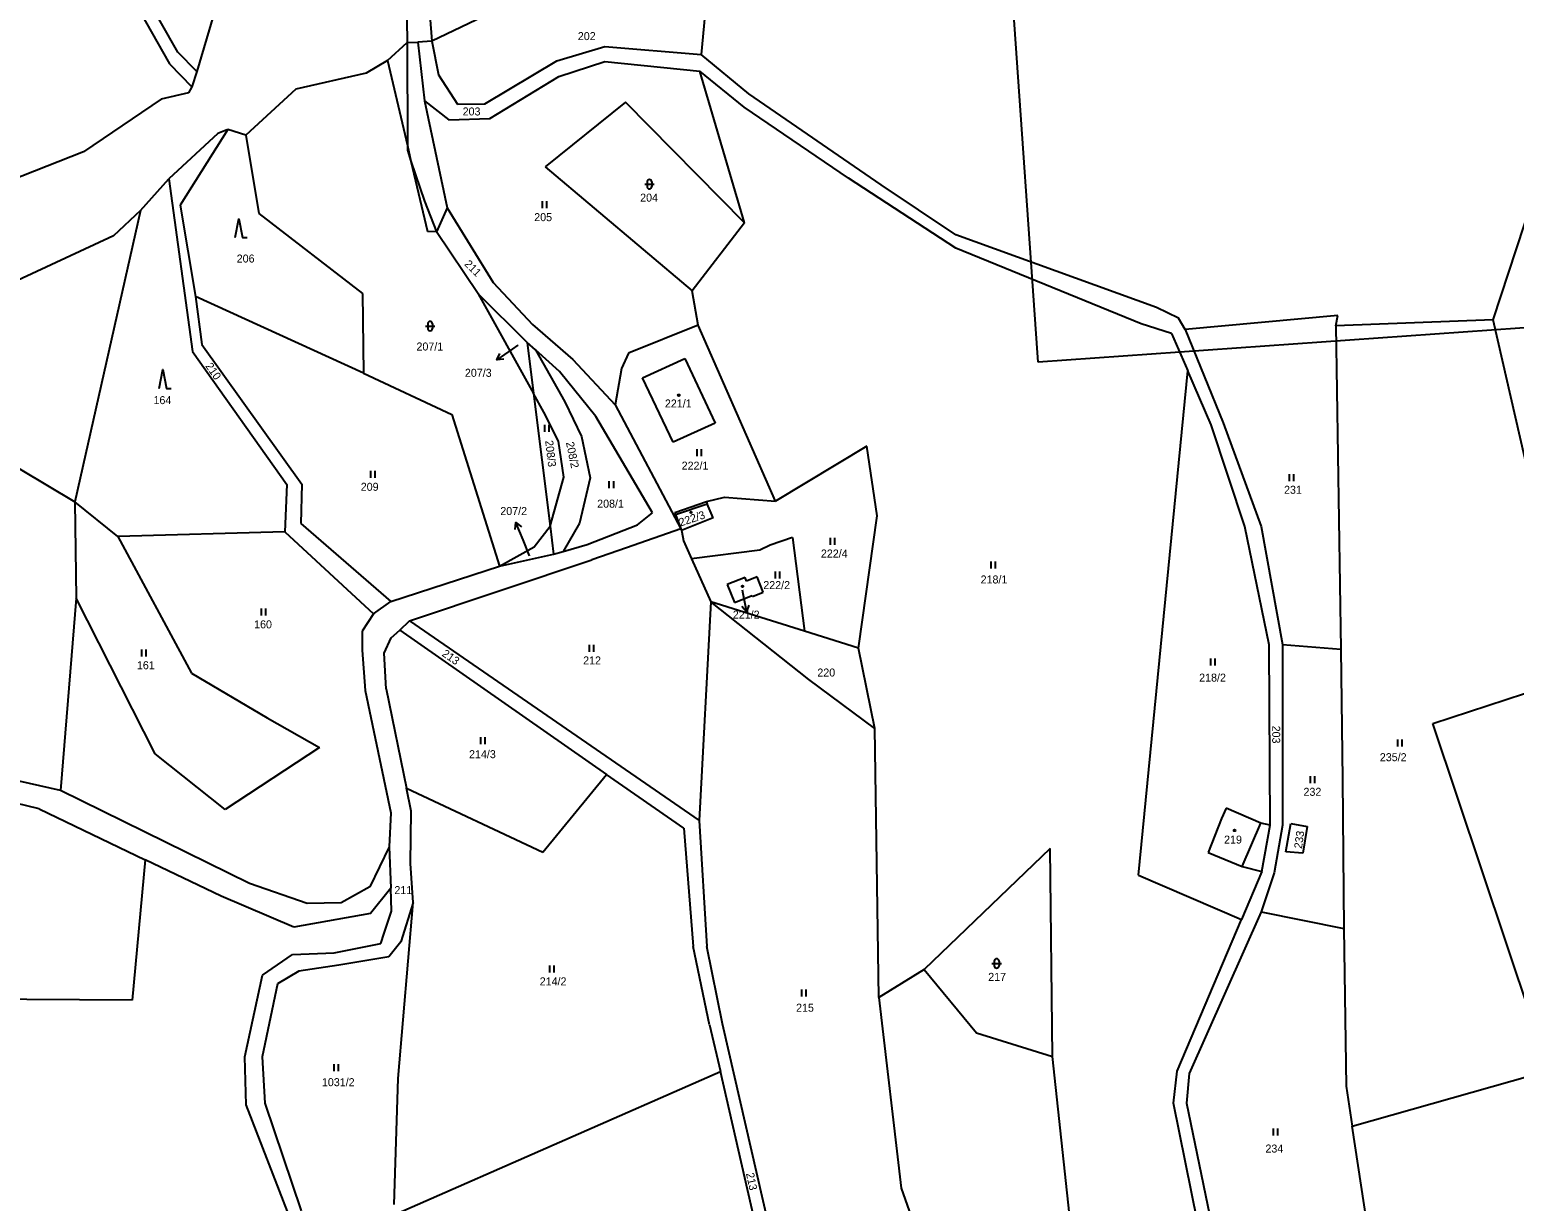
# Model space of a CAD drawing. Extents: x -670359 to -668019, y -978807 to -976674.
# Drawn here: x -669891.1 to -669575.5, y -977465.8 to -977216.7 of the extents above; entities that cross this region are included whole.
import ezdxf

# ---------------------------------------------------------------- set-up
doc = ezdxf.new("R2010")
doc.units = 0
for name, color, linetype in [('Hranice parcel', 7, 'Continuous'), ('Parcelní čísla', 7, 'Continuous'), ('Vnitřní kresba', 7, 'Continuous'), ('Značky budov', 7, 'Continuous'), ('Značky kultur', 7, 'Continuous')]:
    doc.layers.add(name, color=color, linetype=linetype)

msp = doc.modelspace()

# ---------------------------------------------------------------- linework, layer by layer
at = {"layer": 'Defpoints'}
for p, q in [((-669676.69, -977287.4), (-669697.04, -976999.11)), ((-669257.73, -977257.82), (-669676.69, -977287.4))]:
    msp.add_line(p, q, dxfattribs=at)
at = {"layer": 'Hranice parcel'}
for p, q in [((-669739.01, -977333.17), (-669742.81, -977334.66)), ((-669738.72, -977333.92), (-669739.01, -977333.17)), ((-669736.45, -977333.03), (-669738.72, -977333.92)), ((-669735.16, -977336.25), (-669736.45, -977333.03)), ((-669742.81, -977334.66), (-669741.28, -977338.46)), ((-669737.46, -977337.16), (-669735.16, -977336.25)), ((-669741.28, -977338.46), (-669737.54, -977336.98)), ((-669737.54, -977336.98), (-669737.46, -977337.16))]:
    msp.add_line(p, q, dxfattribs=at)
for points in [[(-669745.97, -977196.23), (-669748.39, -977221.98)], [(-669873.73, -977202.11), (-669861.38, -977223.93)], [(-669859.63, -977221.44), (-669870.61, -977202.09)], [(-669780.54, -977207.07), (-669805.6, -977219.15)], [(-669852, -977213.57), (-669855.6, -977225.55)], [(-669805.6, -977219.15), (-669808.62, -977219.32)], [(-669808.62, -977219.32), (-669807.2, -977231.84)], [(-669805.6, -977219.15), (-669804.19, -977226.31)], [(-669855.6, -977225.55), (-669859.63, -977221.44)], [(-669779.01, -977223.28), (-669768.87, -977220.26)], [(-669768.87, -977220.26), (-669748.39, -977221.98)], [(-669738.19, -977230.31), (-669748.39, -977221.98)], [(-669861.38, -977223.93), (-669856.65, -977228.85)], [(-669855.6, -977225.55), (-669856.65, -977228.85)], [(-669819.61, -977225.91), (-669834.51, -977229.35)], [(-669815.03, -977223.23), (-669819.61, -977225.91)], [(-669815.03, -977223.23), (-669810.82, -977241.3)], [(-669794.32, -977232.48), (-669779.01, -977223.28)], [(-669778.6, -977226.63), (-669768.86, -977223.46)], [(-669768.86, -977223.46), (-669748.61, -977225.5)], [(-669739.21, -977233.19), (-669748.61, -977225.5)], [(-669739.16, -977257.72), (-669748.61, -977225.5)], [(-669856.65, -977228.85), (-669857.35, -977230.1)], [(-669804.19, -977226.31), (-669800.16, -977232.52)], [(-669793.26, -977235.59), (-669778.6, -977226.63)], [(-669863.14, -977231.48), (-669879.68, -977242.68)], [(-669857.35, -977230.1), (-669863.14, -977231.48)], [(-669834.51, -977229.35), (-669845.14, -977239.1)], [(-669807.2, -977231.84), (-669802.36, -977254.58)], [(-669807.2, -977231.84), (-669801.98, -977235.88)], [(-669764.41, -977232.06), (-669781.53, -977245.83)], [(-669739.16, -977257.72), (-669764.41, -977232.06)], [(-669710.1, -977249.64), (-669738.19, -977230.31)], [(-669800.16, -977232.52), (-669794.32, -977232.48)], [(-669717.06, -977248.24), (-669739.21, -977233.19)], [(-669848.97, -977237.91), (-669859.14, -977253.96)], [(-669848.97, -977237.91), (-669851.13, -977238.73)], [(-669845.14, -977239.1), (-669848.97, -977237.91)], [(-669801.98, -977235.88), (-669793.26, -977235.59)], [(-669851.13, -977238.73), (-669861.56, -977248.4)], [(-669845.14, -977239.1), (-669842.41, -977255.78)], [(-669810.82, -977241.3), (-669810.05, -977244.62)], [(-669879.68, -977242.68), (-669903.28, -977251.92)], [(-669810.05, -977244.62), (-669806.57, -977259.56)], [(-669781.53, -977245.83), (-669750.28, -977272.17)], [(-669867.54, -977255.16), (-669861.56, -977248.4)], [(-669861.56, -977248.4), (-669856.49, -977285.11)], [(-669694.19, -977263.13), (-669717.06, -977248.24)], [(-669694.2, -977260.33), (-669710.1, -977249.64)], [(-669579.99, -977278.35), (-669570.08, -977248.16)], [(-669859.14, -977253.96), (-669855.83, -977273.44)], [(-669867.54, -977255.16), (-669881.51, -977317.07)], [(-669867.54, -977255.16), (-669873.27, -977260.54)], [(-669842.41, -977255.78), (-669820.33, -977272.75)], [(-669802.36, -977254.58), (-669804.65, -977259.63)], [(-669802.36, -977254.58), (-669792.59, -977270.43)], [(-669873.27, -977260.54), (-669899.87, -977272.82)], [(-669804.65, -977259.63), (-669806.57, -977259.56)], [(-669795.78, -977272.85), (-669804.65, -977259.63)], [(-669739.16, -977257.72), (-669750.28, -977272.17)], [(-669651.58, -977275.74), (-669694.2, -977260.33)], [(-669654.84, -977279.2), (-669694.19, -977263.13)], [(-669820.33, -977272.75), (-669820.16, -977289.69)], [(-669795.78, -977272.85), (-669783.98, -977294.05)], [(-669785.33, -977283.17), (-669795.78, -977272.85)], [(-669792.59, -977270.43), (-669784.23, -977279.33)], [(-669749.03, -977279.5), (-669750.28, -977272.17)], [(-669855.83, -977273.44), (-669854.5, -977283.58)], [(-669820.16, -977289.69), (-669855.83, -977273.44)], [(-669646.85, -977278.03), (-669651.58, -977275.74)], [(-669784.23, -977279.33), (-669775.63, -977286.79)], [(-669749.03, -977279.5), (-669763.8, -977285.44)], [(-669732.56, -977316.93), (-669749.03, -977279.5)], [(-669648.35, -977281.24), (-669654.84, -977279.2)], [(-669645.47, -977280.42), (-669646.85, -977278.03)], [(-669613.02, -977277.43), (-669645.47, -977280.42)], [(-669613.41, -977279.67), (-669613.02, -977277.43)], [(-669579.99, -977278.35), (-669613.41, -977279.67)], [(-669613.41, -977279.67), (-669612.4, -977348.39)], [(-669568.52, -977328.39), (-669579.99, -977278.35)], [(-669648.35, -977281.24), (-669644.9, -977289.2)], [(-669645.47, -977280.42), (-669637.37, -977300.27)], [(-669856.49, -977285.11), (-669836.43, -977313.36)], [(-669854.5, -977283.58), (-669833.23, -977313.34)], [(-669783.61, -977284.73), (-669785.33, -977283.17)], [(-669785.33, -977283.17), (-669783.98, -977294.05)], [(-669783.61, -977284.73), (-669777.31, -977295.79), (-669773.81, -977303.17), (-669771.93, -977311.94), (-669774.22, -977321.62), (-669777.7, -977327.62)], [(-669778.5, -977289.36), (-669783.61, -977284.73)], [(-669763.8, -977285.44), (-669765.3, -977288.73)], [(-669775.63, -977286.79), (-669766.62, -977296.41)], [(-669765.3, -977288.73), (-669766.62, -977296.41)], [(-669760.82, -977290.7), (-669751.8, -977286.57)], [(-669751.8, -977286.57), (-669745.41, -977300.35)], [(-669928.04, -977289.3), (-669881.51, -977317.07)], [(-669820.16, -977289.69), (-669801.4, -977298.53)], [(-669770.77, -977298.91), (-669778.5, -977289.36)], [(-669754.34, -977304.4), (-669760.82, -977290.7)], [(-669655.39, -977396.43), (-669644.9, -977289.2)], [(-669639.93, -977300.68), (-669644.9, -977289.2)], [(-669783.98, -977294.05), (-669780.47, -977322.26)], [(-669780.47, -977322.26), (-669777.53, -977311.83), (-669778.67, -977304.18), (-669781.79, -977297.97), (-669783.98, -977294.05)], [(-669801.4, -977298.53), (-669791.23, -977330.75)], [(-669766.62, -977296.41), (-669752.68, -977322.83)], [(-669758.69, -977319.41), (-669770.77, -977298.91)], [(-669745.41, -977300.35), (-669754.34, -977304.4)], [(-669632.77, -977322.3), (-669639.93, -977300.68)], [(-669637.37, -977300.27), (-669629.33, -977322.28)], [(-669713.15, -977305.2), (-669732.56, -977316.93)], [(-669710.92, -977320.05), (-669713.15, -977305.2)], [(-669836.43, -977313.36), (-669836.85, -977323.44)], [(-669833.23, -977313.34), (-669833.5, -977321.66)], [(-669881.51, -977317.07), (-669881.24, -977337.52)], [(-669872.35, -977324.45), (-669881.51, -977317.07)], [(-669753.94, -977319.34), (-669747.24, -977316.99)], [(-669747.24, -977316.99), (-669743.4, -977316.09)], [(-669747.24, -977316.99), (-669747.08, -977317.47)], [(-669745.78, -977320.48), (-669747.08, -977317.47)], [(-669743.4, -977316.09), (-669732.56, -977316.93)], [(-669761.88, -977321.94), (-669758.69, -977319.41)], [(-669753.94, -977319.34), (-669753.8, -977319.74)], [(-669753.8, -977319.74), (-669752.68, -977322.83)], [(-669745.78, -977320.48), (-669752.56, -977323.17)], [(-669714.94, -977348.16), (-669710.92, -977320.05)], [(-669836.85, -977323.44), (-669872.35, -977324.45)], [(-669836.85, -977323.44), (-669818.04, -977340.9)], [(-669833.5, -977321.66), (-669814.3, -977338.24)], [(-669791.23, -977330.75), (-669783.88, -977326.62), (-669780.47, -977322.26)], [(-669780.47, -977322.26), (-669779.73, -977328.21)], [(-669772.6, -977326.15), (-669761.88, -977321.94)], [(-669752.68, -977322.83), (-669764.26, -977326.84), (-669771.57, -977329.37)], [(-669752.68, -977322.83), (-669752.56, -977323.17)], [(-669752.56, -977323.17), (-669752.48, -977323.41)], [(-669752.48, -977323.41), (-669752.15, -977325.33)], [(-669627.6, -977347.44), (-669632.77, -977322.3)], [(-669629.33, -977322.28), (-669624.8, -977347.42)], [(-669872.35, -977324.45), (-669856.68, -977353.52)], [(-669777.7, -977327.62), (-669772.6, -977326.15)], [(-669752.15, -977325.33), (-669750.41, -977329.18)], [(-669733.67, -977326.26), (-669735.91, -977327.31)], [(-669728.96, -977324.63), (-669733.67, -977326.26)], [(-669728.96, -977324.63), (-669726.39, -977344.56)], [(-669810.36, -977342.38), (-669771.57, -977329.37)], [(-669791.23, -977330.75), (-669779.73, -977328.21)], [(-669779.73, -977328.21), (-669777.7, -977327.62)], [(-669735.91, -977327.31), (-669750.41, -977329.18)], [(-669750.41, -977329.18), (-669746.32, -977338.31)], [(-669814.3, -977338.24), (-669791.23, -977330.75)], [(-669881.24, -977337.52), (-669884.54, -977378.46)], [(-669864.43, -977370.67), (-669881.24, -977337.52)], [(-669818.04, -977340.9), (-669814.3, -977338.24)], [(-669746.32, -977338.31), (-669748.79, -977384.84)], [(-669726.39, -977344.56), (-669746.32, -977338.31)], [(-669725.44, -977354.82), (-669746.32, -977338.31)], [(-669818.04, -977340.9), (-669820.42, -977344.59)], [(-669812.43, -977344.31), (-669810.36, -977342.38)], [(-669810.36, -977342.38), (-669748.79, -977384.84)], [(-669820.42, -977344.59), (-669820.4, -977348.59)], [(-669814.26, -977346), (-669812.43, -977344.31)], [(-669812.43, -977344.31), (-669768.46, -977375.01)], [(-669714.94, -977348.16), (-669726.39, -977344.56)], [(-669820.4, -977348.59), (-669819.8, -977357.14)], [(-669815.76, -977349.2), (-669814.26, -977346)], [(-669711.47, -977365.28), (-669714.94, -977348.16)], [(-669627.39, -977385.8), (-669627.6, -977347.44)], [(-669624.8, -977347.42), (-669624.75, -977385.78)], [(-669624.8, -977347.42), (-669612.4, -977348.39)], [(-669612.4, -977348.39), (-669612.01, -977376.12)], [(-669815.32, -977356.79), (-669815.76, -977349.2)], [(-669856.68, -977353.52), (-669840.64, -977363.01)], [(-669711.47, -977365.28), (-669725.44, -977354.82)], [(-669819.8, -977357.14), (-669814.3, -977383.16)], [(-669815.32, -977356.79), (-669810.99, -977377.91)], [(-669592.8, -977364.17), (-669573.32, -977357.82)], [(-669840.64, -977363.01), (-669829.49, -977369.26)], [(-669571.83, -977426.86), (-669592.8, -977364.17)], [(-669710.6, -977422.41), (-669711.47, -977365.28)], [(-669849.57, -977382.49), (-669864.43, -977370.67)], [(-669829.49, -977369.26), (-669849.57, -977382.49)], [(-669884.54, -977378.46), (-669899.99, -977374.96)], [(-669782.05, -977391.57), (-669768.46, -977375.01)], [(-669752.06, -977386.46), (-669768.46, -977375.01)], [(-669612.01, -977376.12), (-669611.76, -977407.76)], [(-669889.07, -977382.32), (-669901.73, -977379.28)], [(-669844.36, -977398.2), (-669884.54, -977378.46)], [(-669809.98, -977382.81), (-669810.99, -977377.91)], [(-669810.99, -977377.91), (-669782.05, -977391.57)], [(-669889.07, -977382.32), (-669866.53, -977393.14)], [(-669814.3, -977383.16), (-669814.66, -977390.43)], [(-669810.16, -977393.92), (-669809.98, -977382.81)], [(-669636.77, -977382.18), (-669637.73, -977384.37)], [(-669629.39, -977385.41), (-669636.77, -977382.18)], [(-669752.06, -977386.46), (-669750.09, -977411.62)], [(-669748.79, -977384.84), (-669747.13, -977411.6)], [(-669637.73, -977384.37), (-669640.55, -977391.63)], [(-669627.39, -977385.8), (-669629.39, -977385.41)], [(-669629.18, -977395.64), (-669627.39, -977385.8)], [(-669624.75, -977385.78), (-669626.54, -977395.94)], [(-669624.08, -977391.45), (-669622.99, -977385.45)], [(-669622.99, -977385.45), (-669619.55, -977386.07)], [(-669619.55, -977386.07), (-669620.48, -977391.75)], [(-669866.53, -977393.14), (-669869.36, -977423.01)], [(-669850.43, -977400.87), (-669866.53, -977393.14)], [(-669814.66, -977390.43), (-669818.77, -977398.92)], [(-669814.66, -977390.43), (-669814.35, -977399.19)], [(-669674.15, -977390.79), (-669700.96, -977416.52)], [(-669673.67, -977434.98), (-669674.15, -977390.79)], [(-669640.55, -977391.63), (-669633.34, -977394.62)], [(-669620.48, -977391.75), (-669624.08, -977391.45)], [(-669809.56, -977402.23), (-669810.16, -977393.92)], [(-669655.39, -977396.43), (-669633.52, -977405.89)], [(-669629.18, -977395.64), (-669633.52, -977405.89)], [(-669633.34, -977394.62), (-669629.18, -977395.64)], [(-669626.54, -977395.94), (-669629.29, -977404.19)], [(-669832.11, -977402.44), (-669844.36, -977398.2)], [(-669818.77, -977398.92), (-669824.91, -977402.32)], [(-669814.35, -977399.19), (-669818.66, -977404.6)], [(-669814.18, -977404.09), (-669814.35, -977399.19)], [(-669834.96, -977407.49), (-669850.43, -977400.87)], [(-669824.91, -977402.32), (-669832.11, -977402.44)], [(-669812.79, -977439.64), (-669809.56, -977402.23)], [(-669809.56, -977402.23), (-669812.23, -977410.63)], [(-669818.66, -977404.6), (-669834.96, -977407.49)], [(-669815.76, -977408.74), (-669814.18, -977404.09)], [(-669647.18, -977438.1), (-669633.52, -977405.89)], [(-669629.29, -977404.19), (-669644.62, -977438.56)], [(-669629.29, -977404.19), (-669611.76, -977407.76)], [(-669816.47, -977410.98), (-669815.76, -977408.74)], [(-669611.76, -977407.76), (-669611.26, -977441.32)], [(-669826.37, -977412.95), (-669816.47, -977410.98)], [(-669812.23, -977410.63), (-669814.77, -977413.76)], [(-669746.56, -977428.22), (-669750.09, -977411.62)], [(-669743.84, -977428.05), (-669747.13, -977411.6)], [(-669841.62, -977417.68), (-669835.25, -977413.33)], [(-669835.25, -977413.33), (-669826.37, -977412.95)], [(-669814.77, -977413.76), (-669825.4, -977415.59)], [(-669845.37, -977435.04), (-669841.62, -977417.68)], [(-669833.87, -977416.84), (-669838.41, -977419.5)], [(-669825.4, -977415.59), (-669833.87, -977416.84)], [(-669700.96, -977416.52), (-669710.6, -977422.41)], [(-669700.96, -977416.52), (-669689.85, -977429.96)], [(-669838.41, -977419.5), (-669841.69, -977435.02)], [(-669869.36, -977423.01), (-669958.87, -977422.47)], [(-669710.6, -977422.41), (-669705.83, -977462.98)], [(-669746.56, -977428.22), (-669744.27, -977438.16)], [(-669731.56, -977481.43), (-669743.84, -977428.05)], [(-669689.85, -977429.96), (-669673.67, -977434.98)], [(-669609.96, -977449.78), (-669546.2, -977431.72)], [(-669845.07, -977445.27), (-669845.37, -977435.04)], [(-669841.69, -977435.02), (-669841.15, -977444.93)], [(-669667.44, -977492.96), (-669673.67, -977434.98)], [(-669813.61, -977466.42), (-669812.79, -977439.64)], [(-669812.71, -977468.21), (-669744.27, -977438.16)], [(-669733.87, -977483.37), (-669744.27, -977438.16)], [(-669647.94, -977444.89), (-669647.18, -977438.1)], [(-669644.62, -977438.56), (-669645.15, -977444.88)], [(-669611.26, -977441.32), (-669609.96, -977449.78)], [(-669835.84, -977469.21), (-669845.07, -977445.27)], [(-669841.15, -977444.93), (-669833.41, -977467.78)], [(-669638.99, -977489.03), (-669647.94, -977444.89)], [(-669645.15, -977444.88), (-669636.28, -977488.14)], [(-669606.12, -977474.85), (-669609.96, -977449.78)], [(-669705.83, -977462.98), (-669686.33, -977518.16)]]:
    msp.add_lwpolyline(points, dxfattribs=at)
at = {"layer": 'Parcelní čísla'}
for p, q in [((-669787.35, -977283.77), (-669788.51, -977284.58)), ((-669790.3, -977286.74), (-669791.79, -977286.86)), ((-669787.93, -977322.95), (-669787.73, -977321.47)), ((-669784.84, -977328.55), (-669786.22, -977325.17)), ((-669739.66, -977335.8), (-669739.51, -977336.53)), ((-669738.22, -977339.02), (-669738.69, -977340.44))]:
    msp.add_line(p, q, dxfattribs=at)
for points in [[(-669788.51, -977284.58), (-669791.79, -977286.86), (-669791.16, -977285.5)], [(-669786.22, -977325.17), (-669787.73, -977321.47), (-669786.54, -977322.39)], [(-669739.51, -977336.53), (-669738.69, -977340.44), (-669739.69, -977339.33)]]:
    msp.add_lwpolyline(points, dxfattribs=at)
at = {"layer": 'Vnitřní kresba'}
for points in [[(-669807.3, -977197.24), (-669805.6, -977219.15)], [(-669811.13, -977199.58), (-669810.87, -977219.4)], [(-669815.03, -977223.23), (-669810.87, -977219.4)], [(-669810.87, -977219.4), (-669808.62, -977219.32)], [(-669810.87, -977219.4), (-669810.82, -977241.3)], [(-669810.82, -977241.3), (-669810.82, -977242.33)], [(-669810.82, -977242.33), (-669810.05, -977244.62)], [(-669810.05, -977244.62), (-669807.16, -977253.17)], [(-669807.16, -977253.17), (-669804.65, -977259.63)], [(-669753.8, -977319.74), (-669747.08, -977317.47)], [(-669633.34, -977394.62), (-669629.39, -977385.41)]]:
    msp.add_lwpolyline(points, dxfattribs=at)
at = {"layer": 'Značky budov'}
for centre in [(-669753.11, -977294.4), (-669750.51, -977319.29), (-669739.57, -977335.02), (-669634.96, -977386.93)]:
    msp.add_circle(centre, 0.175, dxfattribs=at)
at = {"layer": 'Značky kultur'}
for p, q in [((-669760.37, -977249.54), (-669758.37, -977249.54)), ((-669759.87, -977249.04), (-669759.87, -977250.04)), ((-669758.87, -977249.04), (-669758.87, -977250.04)), ((-669782.15, -977253.12), (-669782.15, -977254.62)), ((-669781.15, -977254.62), (-669781.15, -977253.12)), ((-669806.48, -977279.21), (-669806.48, -977280.21)), ((-669805.48, -977279.21), (-669805.48, -977280.21)), ((-669806.98, -977279.71), (-669804.98, -977279.71)), ((-669781.69, -977300.68), (-669781.69, -977302.18)), ((-669780.69, -977302.18), (-669780.69, -977300.68)), ((-669749.28, -977305.88), (-669749.28, -977307.38)), ((-669748.28, -977307.38), (-669748.28, -977305.88)), ((-669818.63, -977310.45), (-669818.63, -977311.95)), ((-669817.63, -977311.95), (-669817.63, -977310.45)), ((-669623.33, -977311.15), (-669623.33, -977312.65)), ((-669622.33, -977312.65), (-669622.33, -977311.15)), ((-669767.96, -977312.68), (-669767.96, -977314.18)), ((-669766.96, -977314.18), (-669766.96, -977312.68)), ((-669720.91, -977324.7), (-669720.91, -977326.2)), ((-669719.91, -977326.2), (-669719.91, -977324.7)), ((-669686.81, -977329.75), (-669686.81, -977331.25)), ((-669685.81, -977331.25), (-669685.81, -977329.75)), ((-669732.65, -977331.88), (-669732.65, -977333.38)), ((-669731.65, -977333.38), (-669731.65, -977331.88)), ((-669841.88, -977339.75), (-669841.88, -977341.25)), ((-669840.88, -977341.25), (-669840.88, -977339.75)), ((-669867.36, -977348.45), (-669867.36, -977349.95)), ((-669866.36, -977349.95), (-669866.36, -977348.45)), ((-669772.16, -977347.43), (-669772.16, -977348.93)), ((-669771.16, -977348.93), (-669771.16, -977347.43)), ((-669640.08, -977350.35), (-669640.08, -977351.85)), ((-669639.08, -977351.85), (-669639.08, -977350.35)), ((-669795.26, -977367.08), (-669795.26, -977368.58)), ((-669794.26, -977368.58), (-669794.26, -977367.08)), ((-669600.31, -977367.56), (-669600.31, -977369.06)), ((-669599.31, -977369.06), (-669599.31, -977367.56)), ((-669618.88, -977375.36), (-669618.88, -977376.86)), ((-669617.88, -977376.86), (-669617.88, -977375.36)), ((-669686.54, -977415.2), (-669684.54, -977415.2)), ((-669686.04, -977414.7), (-669686.04, -977415.7)), ((-669685.04, -977414.7), (-669685.04, -977415.7)), ((-669780.62, -977415.6), (-669780.62, -977417.1)), ((-669779.62, -977417.1), (-669779.62, -977415.6)), ((-669727.05, -977420.72), (-669727.05, -977422.22)), ((-669726.05, -977422.22), (-669726.05, -977420.72)), ((-669826.44, -977436.59), (-669826.44, -977438.09)), ((-669825.44, -977438.09), (-669825.44, -977436.59)), ((-669626.75, -977450.28), (-669626.75, -977451.78)), ((-669625.75, -977451.78), (-669625.75, -977450.28))]:
    msp.add_line(p, q, dxfattribs=at)
for points in [[(-669847.4, -977260.9), (-669846.65, -977256.9), (-669845.9, -977260.9), (-669844.9, -977260.9)], [(-669863.56, -977292.94), (-669862.81, -977288.94), (-669862.06, -977292.94), (-669861.06, -977292.94)]]:
    msp.add_lwpolyline(points, dxfattribs=at)
for centre in [(-669753.11, -977294.4), (-669750.51, -977319.29), (-669739.57, -977335.02), (-669634.96, -977386.93)]:
    msp.add_circle(centre, 0.175, dxfattribs=at)
for centre, start, end in [((-669759.37, -977249.04), 0, 180), ((-669759.37, -977250.04), 180, 0), ((-669805.98, -977279.21), 0, 180), ((-669805.98, -977280.21), 180, 0), ((-669685.54, -977414.7), 0, 180), ((-669685.54, -977415.7), 180, 0)]:
    msp.add_arc(centre, 0.5, start, end, dxfattribs=at)

# ---------------------------------------------------------------- texts
at = {"layer": 'Parcelní čísla'}
for s, height, p in [('202', 1.7, (-669774.58, -977218.9)), ('203', 1.7, (-669799.07, -977234.92)), ('204', 1.7, (-669761.33, -977253.24)), ('205', 1.7, (-669783.85, -977257.39)), ('206', 1.7, (-669847.1, -977266.19)), ('207/1', 1.7, (-669808.88, -977284.89)), ('207/3', 0.1, (-669787.55, -977283.77)), ('207/3', 1.7, (-669798.59, -977290.48)), ('164', 1.7, (-669864.79, -977296.29)), ('221/1', 1.7, (-669756.07, -977297)), ('222/1', 1.7, (-669752.51, -977310.22)), ('209', 1.7, (-669820.73, -977314.71)), ('231', 1.7, (-669624.44, -977315.35)), ('208/1', 1.7, (-669770.47, -977318.3)), ('207/2', 1.7, (-669791.06, -977319.87)), ('207/2', 0.1, (-669785.04, -977328.55)), ('222/4', 1.7, (-669722.9, -977328.9)), ('218/1', 1.7, (-669688.95, -977334.42)), ('221/2', 0.1, (-669739.66, -977335.8)), ('222/2', 1.7, (-669735.15, -977335.61)), ('160', 1.7, (-669843.4, -977343.96)), ('221/2', 1.7, (-669741.63, -977341.9)), ('161', 1.7, (-669868.32, -977352.65)), ('212', 1.7, (-669773.45, -977351.63)), ('220', 1.7, (-669723.66, -977354.2)), ('218/2', 1.7, (-669642.49, -977355.28)), ('214/3', 1.7, (-669797.71, -977371.56)), ('235/2', 1.7, (-669604.08, -977372.2)), ('232', 1.7, (-669620.31, -977379.56)), ('219', 1.7, (-669637.19, -977389.72)), ('211', 1.7, (-669813.58, -977400.46)), ('214/2', 1.7, (-669782.68, -977419.86)), ('217', 1.7, (-669687.33, -977418.9)), ('215', 1.7, (-669728.18, -977425.46)), ('1031/2', 1.7, (-669828.99, -977441.29)), ('234', 1.7, (-669628.4, -977455.4))]:
    msp.add_text(s, height=height, dxfattribs=at).set_placement(p)
for s, rotation, p in [('211', 315, (-669798.82, -977266.65)), ('210', 304.3652, (-669853.83, -977288.19)), ('208/3', 276.7492, (-669781.53, -977304.07)), ('208/2', 281.5621, (-669777.11, -977304.46)), ('222/3', 18.3448, (-669752.76, -977322.32)), ('213', 325.3591, (-669803.61, -977349.7)), ('203', 269.8197, (-669626.95, -977364.64)), ('233', 82.0565, (-669620.64, -977390.88)), ('213', 282.1442, (-669738.84, -977459.86))]:
    msp.add_text(s, height=1.7, rotation=rotation, dxfattribs=at).set_placement(p)

doc.saveas('drawing.dxf')
